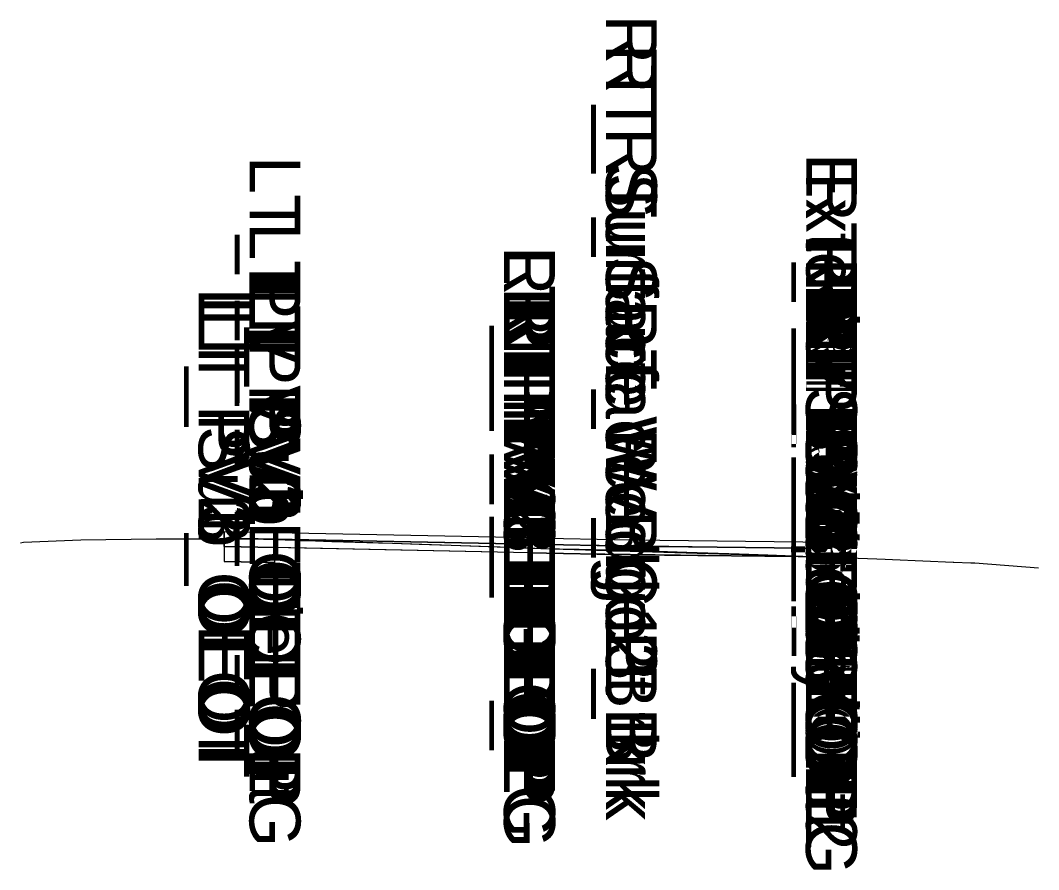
# Model space of a CAD drawing. Extents: x -26 to 3240, y -10 to 12522.
# Drawn here: x 2200 to 2240, y 3989.6 to 4022.94 of the extents above; entities that cross this region are included whole.
import ezdxf

# ---------------------------------------------------------------- set-up
doc = ezdxf.new("R2010")
doc.units = 0
for name, color, linetype in [('Default', 7, 'Continuous'), ('Exist CMT Pavement', 7, 'Continuous'), ('Exist XS Ground Line', 7, 'Continuous'), ('Prop CMT DNC', 7, 'Continuous'), ('Prop CMT Pvmt Course 1', 7, 'Continuous'), ('Prop CMT Pvmt Course 1 Wedge', 7, 'Continuous'), ('Prop CMT Pvmt Course 2', 7, 'Continuous'), ('Prop CMT Pvmt Course 2 Wedge', 7, 'Continuous'), ('Prop CMT Pvmt Course 3', 7, 'Continuous'), ('Prop CMT Pvmt Course 3 Wedge', 7, 'Continuous'), ('Prop CMT Pvmt Surface', 7, 'Continuous'), ('Prop CMT Pvmt Wedge Surface 1', 7, 'Continuous'), ('Prop CMT Pvmt Wedge Surface 2', 7, 'Continuous'), ('Prop CMT Pvmt Wedge Surface 3', 7, 'Continuous'), ('Prop CMT Shear Line', 7, 'Continuous'), ('Prop CMT Subgrade Earthwork', 7, 'Continuous'), ('Scratch_Level_0', 7, 'Continuous')]:
    doc.layers.add(name, color=color, linetype=linetype)

msp = doc.modelspace()

# ---------------------------------------------------------------- linework, layer by layer
at = {"layer": 'Exist CMT Pavement'}
for points in [[(2219.999, 4002.22), (2210.002, 4002.553)], [(2220.002, 4002.22), (2231.858, 4001.863)]]:
    msp.add_lwpolyline(points, dxfattribs=at)
at = {"layer": 'Exist XS Ground Line'}
msp.add_lwpolyline([(2200, 4002.432), (2200.124, 4002.446), (2202.377, 4002.54), (2205.331, 4002.579), (2205.751, 4002.579), (2205.854, 4002.58), (2206.372, 4002.58), (2208.4, 4002.585), (2209.097, 4002.581), (2209.119, 4002.58), (2210.826, 4002.528), (2210.964, 4002.523), (2211.262, 4002.514), (2212.234, 4002.484), (2214.068, 4002.428), (2214.627, 4002.411), (2215.67, 4002.377), (2216.483, 4002.35), (2216.918, 4002.335), (2218.375, 4002.279), (2219.772, 4002.227), (2220.644, 4002.2), (2221.182, 4002.185), (2221.954, 4002.175), (2222.574, 4002.162), (2224.511, 4002.106), (2225.418, 4002.08), (2226.181, 4002.056), (2228.241, 4001.99), (2229.368, 4001.953), (2231.081, 4001.891), (2231.215, 4001.886), (2231.462, 4001.877), (2233.644, 4001.8), (2233.972, 4001.788), (2234.263, 4001.771), (2236.642, 4001.669), (2236.675, 4001.668), (2237.342, 4001.64), (2237.5, 4001.636), (2240, 4001.443)], dxfattribs=at)
at = {"layer": 'Prop CMT DNC'}
msp.add_lwpolyline([(2231.86, 4001.291), (2231.86, 4002.791)], dxfattribs=at)
at = {"layer": 'Prop CMT Pvmt Course 1'}
for points in [[(2220, 4002.621), (2208, 4002.861)], [(2208, 4002.861), (2208, 4002.611)], [(2208, 4002.611), (2210, 4002.571)], [(2210, 4002.571), (2210, 4002.571)], [(2210, 4002.571), (2220, 4002.371)], [(2220, 4002.371), (2220, 4002.621)], [(2220, 4002.621), (2224, 4002.541), (2231.86, 4002.458)], [(2220, 4002.371), (2220, 4002.621)], [(2231.86, 4002.458), (2231.86, 4002.208), (2231.86, 4002.208), (2231.86, 4002.208)], [(2220, 4002.371), (2220, 4002.371), (2220, 4002.371)], [(2231.86, 4002.208), (2224, 4002.291), (2220, 4002.371)], [(2220, 4002.371), (2220, 4002.371), (2220, 4002.371)]]:
    msp.add_lwpolyline(points, dxfattribs=at)
at = {"layer": 'Prop CMT Pvmt Course 1 Wedge'}
for points in [[(2220, 4002.371), (2210, 4002.571)], [(2224, 4002.291), (2220, 4002.371)], [(2220, 4002.371), (2231.86, 4002.208)], [(2231.86, 4002.208), (2224, 4002.291)]]:
    msp.add_lwpolyline(points, dxfattribs=at)
at = {"layer": 'Prop CMT Pvmt Course 2'}
for points in [[(2210, 4002.571), (2208, 4002.611)], [(2208, 4002.611), (2208, 4002.277)], [(2210, 4002.237), (2210, 4002.571)], [(2208, 4002.277), (2210, 4002.237)], [(2231.86, 4001.874), (2231.86, 4001.874), (2231.86, 4002.208), (2231.86, 4002.208)], [(2231.86, 4002.208), (2231.86, 4001.874)]]:
    msp.add_lwpolyline(points, dxfattribs=at)
at = {"layer": 'Prop CMT Pvmt Course 2 Wedge'}
for points in [[(2220, 4002.371), (2210, 4002.571)], [(2224, 4002.291), (2220, 4002.371)], [(2220, 4002.371), (2231.86, 4002.208)], [(2231.86, 4002.208), (2224, 4002.291)]]:
    msp.add_lwpolyline(points, dxfattribs=at)
at = {"layer": 'Prop CMT Pvmt Course 3'}
for points in [[(2210, 4002.237), (2208, 4002.277)], [(2208, 4002.277), (2208, 4001.694)], [(2210, 4001.654), (2210, 4002.237)], [(2208, 4001.694), (2210, 4001.654)], [(2231.86, 4001.874), (2231.86, 4001.874), (2231.86, 4001.291), (2231.86, 4001.291)], [(2231.86, 4001.291), (2231.86, 4001.874)]]:
    msp.add_lwpolyline(points, dxfattribs=at)
at = {"layer": 'Prop CMT Pvmt Course 3 Wedge'}
for points in [[(2220, 4002.037), (2210, 4002.237)], [(2224, 4001.957), (2220, 4002.037)], [(2220, 4002.037), (2231.86, 4001.874)], [(2231.86, 4001.874), (2224, 4001.957)]]:
    msp.add_lwpolyline(points, dxfattribs=at)
at = {"layer": 'Prop CMT Pvmt Surface'}
for points in [[(2220, 4002.621), (2208, 4002.861)], [(2220, 4002.621), (2224, 4002.541), (2231.86, 4002.458)]]:
    msp.add_lwpolyline(points, dxfattribs=at)
at = {"layer": 'Prop CMT Pvmt Wedge Surface 1'}
for points in [[(2208, 4002.611), (2208, 4002.861)], [(2210, 4002.571), (2208, 4002.611)], [(2220, 4002.371), (2210, 4002.571)], [(2210, 4002.571), (2210, 4002.571)], [(2231.86, 4002.208), (2231.86, 4002.458)], [(2220, 4002.371), (2224, 4002.291), (2231.86, 4002.208)], [(2231.86, 4002.208), (2231.86, 4002.208), (2231.86, 4002.208)]]:
    msp.add_lwpolyline(points, dxfattribs=at)
at = {"layer": 'Prop CMT Pvmt Wedge Surface 2'}
for points in [[(2208, 4002.611), (2208, 4002.861)], [(2220, 4002.371), (2208, 4002.611)], [(2231.86, 4002.208), (2231.86, 4002.458)], [(2220, 4002.371), (2224, 4002.291), (2231.86, 4002.208)]]:
    msp.add_lwpolyline(points, dxfattribs=at)
at = {"layer": 'Prop CMT Pvmt Wedge Surface 3'}
for points in [[(2208, 4002.277), (2208, 4002.861)], [(2231.86, 4001.874), (2231.86, 4002.458)], [(2220, 4002.037), (2208, 4002.277)], [(2220, 4002.037), (2224, 4001.957), (2231.86, 4001.874)]]:
    msp.add_lwpolyline(points, dxfattribs=at)
at = {"layer": 'Prop CMT Shear Line'}
msp.add_lwpolyline([(2231.86, 4006.291), (2231.86, 3996.291)], dxfattribs=at)
at = {"layer": 'Prop CMT Subgrade Earthwork'}
for points in [[(2210, 4001.654), (2210.002, 4002.553)], [(2210, 4001.654), (2208, 4001.694)], [(2231.86, 4001.291), (2231.858, 4001.863)], [(2231.86, 4001.291), (2231.87, 4001.863)], [(2231.86, 4001.291), (2231.86, 4001.291)]]:
    msp.add_lwpolyline(points, dxfattribs=at)

# ---------------------------------------------------------------- texts
at = {"layer": 'Default'}
msp.add_text('-', height=0.0001, dxfattribs=at).set_placement((2200, 4000))
at = {"layer": 'Scratch_Level_0'}
for s, p in [('RT_ Surface Wedge2_Brk', (2223, 4023.157)), ('RT_Surface Wedge3_Brk', (2223, 4022.004)), ('RT_Surface Brk Pt', (2223, 4018.73)), ('LT_PV_Sub_Tie_Out', (2209.002, 4017.608)), ('Exterior Boundary', (2230.87, 4017.721)), ('RT_PV_Sub_Tie_Out', (2230.858, 4016.966)), ('LT_PV_OEEOP_EG', (2209.002, 4015.01)), ('RT_PV_OEEOP_EG', (2230.858, 4014.367)), ('LT_PV_IEEOP_EG', (2218.999, 4014.031)), ('RT_PV_IEEOP_EG', (2219.002, 4014.078)), ('RT_SL_Pt1', (2230.86, 4013.614)), ('LT_PV2_OEEOP', (2209, 4013.263)), ('LT_PV3_OEEOP', (2209, 4012.93)), ('LT_PV1_OEEOP', (2209, 4012.697)), ('RT_PV2_OEEOP', (2230.86, 4012.948)), ('LT_PV2_OEOT', (2207, 4012.437)), ('LT_Sub_OEEOP', (2209, 4012.441)), ('RT_PV2_IEEOP', (2219, 4012.465)), ('LT_PV2_IEEOP', (2219, 4012.418)), ('RT_PV3_OEEOP', (2230.86, 4012.615)), ('RT_PV1_OEEOP', (2230.86, 4012.381)), ('LT_PV1_OEOT', (2207, 4012.12)), ('LT_PV3_OEOT', (2207, 4012.104)), ('RT_PV3_IEEOP', (2219, 4012.132)), ('LT_PV3_IEEOP', (2219, 4012.084)), ('RT_PV1_IEEOP', (2219, 4011.898)), ('LT_PV1_IEEOP', (2219, 4011.851)), ('RT_PV_C1 Brk', (2223, 4011.976)), ('RT_Sub_OEEOP', (2230.86, 4012.126)), ('RT_PV2_OEOT', (2230.86, 4012.082)), ('RT_SL_Label', (2230.86, 4012.067)), ('LT_Sub_OEOT', (2207, 4011.615)), ('RT_PV1_OEOT', (2230.86, 4011.765)), ('RT_PV3_OEOT', (2230.86, 4011.748)), ('RT_Slope_Fill', (2230.87, 4011.391)), ('RT_Sub_OEOT', (2230.86, 4011.26)), ('PV2_PGL', (2219, 4008.465)), ('PV1_PGL', (2219, 4008.148)), ('RT_SL_Pt2', (2230.86, 4004.181))]:
    msp.add_text(s, height=2, rotation=270, dxfattribs=at).set_placement(p)

doc.saveas('drawing.dxf')
